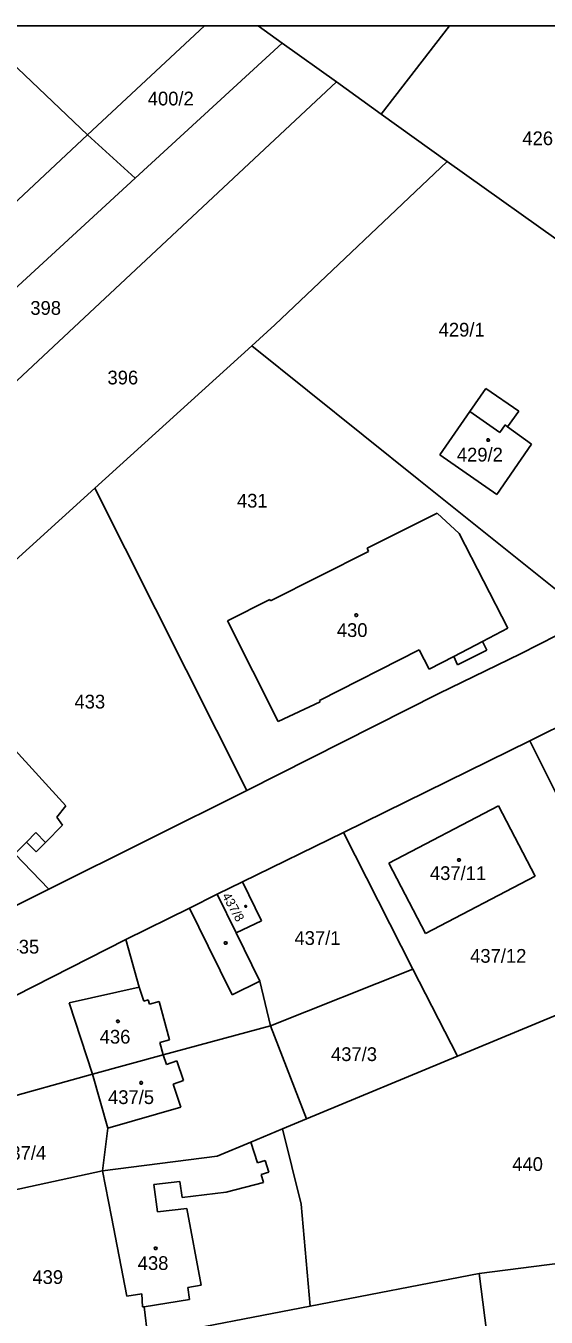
# Model space of a CAD drawing. Extents: x -639621 to -639329, y -1192893 to -1192488.
# Drawn here: x -639495.6 to -639431.2, y -1192647.6 to -1192487.8 of the extents above; entities that cross this region are included whole.
import ezdxf

# ---------------------------------------------------------------- set-up
doc = ezdxf.new("R2010")
doc.units = 0
for name, color, linetype in [('Vrstva 1', 7, 'Continuous'), ('Vrstva 2', 7, 'Continuous'), ('Vrstva 4', 7, 'Continuous'), ('Vrstva 5', 7, 'Continuous'), ('Vrstva 61', 7, 'Continuous')]:
    doc.layers.add(name, color=color, linetype=linetype)

msp = doc.modelspace()

# ---------------------------------------------------------------- linework, layer by layer
at = {"layer": 'Vrstva 1'}
for p, q in [((-639502.15, -1192487.83), (-639487.95, -1192501.33)), ((-639487.95, -1192501.33), (-639473.51, -1192487.83)), ((-639466.87, -1192487.83), (-639463.89, -1192489.96)), ((-639451.66, -1192498.76), (-639443.19, -1192487.83)), ((-639482.08, -1192506.67), (-639463.89, -1192489.96)), ((-639463.89, -1192489.96), (-639457.17, -1192494.75)), ((-639457.17, -1192494.75), (-639502, -1192536.7)), ((-639451.66, -1192498.76), (-639457.17, -1192494.75)), ((-639443.48, -1192504.61), (-639451.66, -1192498.76)), ((-639508.19, -1192520.25), (-639487.95, -1192501.33)), ((-639487.95, -1192501.33), (-639482.08, -1192506.67)), ((-639464.78, -1192524.82), (-639443.48, -1192504.61)), ((-639423.39, -1192518.97), (-639443.48, -1192504.61)), ((-639519.26, -1192540.82), (-639482.08, -1192506.67)), ((-639467.64, -1192527.41), (-639464.78, -1192524.82)), ((-639487.05, -1192545.04), (-639467.64, -1192527.41)), ((-639447, -1192544.01), (-639467.64, -1192527.41)), ((-639440.69, -1192535.56), (-639438.71, -1192532.69)), ((-639438.71, -1192532.69), (-639434.64, -1192535.5)), ((-639444.38, -1192540.91), (-639440.69, -1192535.56)), ((-639434.64, -1192535.5), (-639436.03, -1192537.44)), ((-639436.03, -1192537.44), (-639433.06, -1192539.6)), ((-639433.06, -1192539.6), (-639437.36, -1192545.84)), ((-639437.36, -1192545.84), (-639444.38, -1192540.91)), ((-639425.67, -1192561.08), (-639447, -1192544.01)), ((-639503.65, -1192560.07), (-639487.05, -1192545.04)), ((-639487.05, -1192545.04), (-639468.24, -1192582.43)), ((-639453.4, -1192552.48), (-639444.72, -1192548.13)), ((-639444.72, -1192548.13), (-639442.02, -1192550.64)), ((-639435.99, -1192562.38), (-639442.02, -1192550.64)), ((-639453.2, -1192552.87), (-639453.4, -1192552.48)), ((-639465.33, -1192558.96), (-639453.2, -1192552.87)), ((-639470.65, -1192561.46), (-639465.4, -1192558.83)), ((-639465.4, -1192558.83), (-639465.33, -1192558.96)), ((-639470.65, -1192561.46), (-639464.4, -1192573.92)), ((-639425.67, -1192561.08), (-639434.43, -1192565.52)), ((-639435.99, -1192562.38), (-639439.1, -1192564)), ((-639459.26, -1192571.32), (-639446.93, -1192565.03)), ((-639446.93, -1192565.03), (-639445.72, -1192567.45)), ((-639442.19, -1192566.9), (-639438.6, -1192565.07)), ((-639439.1, -1192564), (-639438.6, -1192565.07)), ((-639442.65, -1192565.85), (-639445.72, -1192567.45)), ((-639434.43, -1192565.52), (-639444.52, -1192570.43)), ((-639442.65, -1192565.85), (-639442.19, -1192566.9)), ((-639433.26, -1192576.32), (-639418.68, -1192568.97)), ((-639444.52, -1192570.43), (-639468.24, -1192582.43)), ((-639464.4, -1192573.92), (-639459.19, -1192571.46)), ((-639459.19, -1192571.46), (-639459.26, -1192571.32)), ((-639456.32, -1192587.64), (-639433.26, -1192576.32)), ((-639433.26, -1192576.32), (-639426.82, -1192589.24)), ((-639497.3, -1192577.02), (-639490.62, -1192584.36)), ((-639468.24, -1192582.43), (-639492.74, -1192594.64)), ((-639490.62, -1192584.36), (-639491.74, -1192585.74)), ((-639437.15, -1192584.36), (-639450.71, -1192591.45)), ((-639432.62, -1192593.04), (-639437.15, -1192584.36)), ((-639491.74, -1192585.74), (-639491.04, -1192586.75)), ((-639491.04, -1192586.75), (-639493.14, -1192588.86)), ((-639468.8, -1192593.76), (-639456.32, -1192587.64)), ((-639456.32, -1192587.64), (-639447.72, -1192604.54)), ((-639496.96, -1192590.28), (-639495.5, -1192588.82)), ((-639495.5, -1192588.82), (-639494.3, -1192590.02)), ((-639493.14, -1192588.86), (-639494.3, -1192590.02)), ((-639492.74, -1192594.64), (-639496.96, -1192590.28)), ((-639450.71, -1192591.45), (-639446.18, -1192600.12)), ((-639471.92, -1192595.29), (-639468.8, -1192593.76)), ((-639466.43, -1192598.56), (-639468.8, -1192593.76)), ((-639446.18, -1192600.12), (-639432.62, -1192593.04)), ((-639492.74, -1192594.64), (-639508.34, -1192602.41)), ((-639475.35, -1192596.99), (-639471.92, -1192595.29)), ((-639471.92, -1192595.29), (-639469.58, -1192600.06)), ((-639483.2, -1192600.88), (-639475.35, -1192596.99)), ((-639469.58, -1192600.06), (-639466.43, -1192598.56)), ((-639469.58, -1192600.06), (-639466.66, -1192606.02)), ((-639506.47, -1192612.71), (-639483.2, -1192600.88)), ((-639483.2, -1192600.88), (-639481.59, -1192606.77)), ((-639465.33, -1192611.56), (-639447.72, -1192604.54)), ((-639447.72, -1192604.54), (-639442.23, -1192615.33)), ((-639442.23, -1192615.33), (-639417.68, -1192605.12)), ((-639490.24, -1192608.71), (-639481.59, -1192606.77)), ((-639466.66, -1192606.02), (-639465.33, -1192611.56)), ((-639487.35, -1192617.54), (-639490.24, -1192608.71)), ((-639478.6, -1192615.16), (-639465.33, -1192611.56)), ((-639465.33, -1192611.56), (-639460.88, -1192623.08)), ((-639487.35, -1192617.54), (-639478.6, -1192615.16)), ((-639460.88, -1192623.08), (-639442.23, -1192615.33)), ((-639504.77, -1192622.38), (-639487.35, -1192617.54)), ((-639487.35, -1192617.54), (-639485.44, -1192624.21)), ((-639485.44, -1192624.21), (-639486.09, -1192629.51)), ((-639467.76, -1192625.94), (-639463.84, -1192624.31)), ((-639463.84, -1192624.31), (-639460.88, -1192623.08)), ((-639463.84, -1192624.31), (-639461.53, -1192633.63)), ((-639467.76, -1192625.94), (-639471.91, -1192627.67)), ((-639486.09, -1192629.51), (-639471.91, -1192627.67)), ((-639502.88, -1192633.13), (-639486.09, -1192629.51)), ((-639486.09, -1192629.51), (-639484.99, -1192635.2)), ((-639460.43, -1192646.25), (-639461.53, -1192633.63)), ((-639484.99, -1192635.2), (-639483.1, -1192645)), ((-639399.34, -1192636.99), (-639439.54, -1192642.21)), ((-639460.43, -1192646.25), (-639439.54, -1192642.21)), ((-639439.54, -1192642.21), (-639433.22, -1192690.86)), ((-639483.1, -1192645), (-639481.24, -1192644.73)), ((-639481.24, -1192644.73), (-639481.16, -1192646.34)), ((-639481.16, -1192646.34), (-639480.96, -1192646.31)), ((-639480.96, -1192646.31), (-639480.51, -1192650.14)), ((-639480.51, -1192650.14), (-639460.43, -1192646.25))]:
    msp.add_line(p, q, dxfattribs=at)
at = {"layer": 'Vrstva 4'}
for p, q in [((-639436.96, -1192538.13), (-639440.69, -1192535.56)), ((-639436.33, -1192537.22), (-639436.96, -1192538.13)), ((-639436.03, -1192537.44), (-639436.33, -1192537.22)), ((-639439.1, -1192564), (-639442.65, -1192565.85)), ((-639495.5, -1192588.82), (-639494.34, -1192587.66)), ((-639494.34, -1192587.66), (-639493.14, -1192588.86)), ((-639475.35, -1192596.99), (-639473.02, -1192601.72)), ((-639473.02, -1192601.72), (-639470.07, -1192607.71)), ((-639481.59, -1192606.77), (-639480.98, -1192608.5)), ((-639466.66, -1192606.02), (-639470.07, -1192607.71)), ((-639480.98, -1192608.5), (-639480.46, -1192608.36)), ((-639480.46, -1192608.36), (-639480.31, -1192608.89)), ((-639479.1, -1192608.56), (-639480.31, -1192608.89)), ((-639477.81, -1192613.29), (-639479.1, -1192608.56)), ((-639479.02, -1192613.62), (-639477.81, -1192613.29)), ((-639479.02, -1192613.62), (-639478.6, -1192615.16)), ((-639478.6, -1192615.16), (-639478.2, -1192616.34)), ((-639476.9, -1192615.9), (-639478.2, -1192616.34)), ((-639476.9, -1192615.9), (-639476.08, -1192618.33)), ((-639476.08, -1192618.33), (-639477.38, -1192618.77)), ((-639477.38, -1192618.77), (-639476.41, -1192621.61)), ((-639485.44, -1192624.21), (-639476.41, -1192621.61)), ((-639467.76, -1192625.94), (-639466.95, -1192628.53)), ((-639465.99, -1192628.23), (-639466.95, -1192628.53)), ((-639465.99, -1192628.23), (-639465.55, -1192629.66)), ((-639479.76, -1192631.18), (-639476.55, -1192630.81)), ((-639476.55, -1192630.81), (-639476.24, -1192632.82)), ((-639465.55, -1192629.66), (-639466.5, -1192629.96)), ((-639466.5, -1192629.96), (-639466.19, -1192630.96)), ((-639479.76, -1192631.18), (-639479.3, -1192634.58)), ((-639476.24, -1192632.82), (-639470.83, -1192632.16)), ((-639470.83, -1192632.16), (-639466.19, -1192630.96)), ((-639479.3, -1192634.58), (-639475.69, -1192634.18)), ((-639473.92, -1192643.67), (-639475.69, -1192634.18)), ((-639473.92, -1192643.67), (-639475.57, -1192643.93)), ((-639475.57, -1192643.93), (-639475.34, -1192645.44)), ((-639480.96, -1192646.31), (-639475.34, -1192645.44))]:
    msp.add_line(p, q, dxfattribs=at)
at = {"layer": 'Vrstva 5'}
for points in [[(-639438.33, -1192538.93), (-639438.24, -1192539.08), (-639438.33, -1192539.23), (-639438.51, -1192539.23), (-639438.6, -1192539.08), (-639438.51, -1192538.93)], [(-639454.64, -1192560.6), (-639454.55, -1192560.75), (-639454.64, -1192560.9), (-639454.82, -1192560.9), (-639454.91, -1192560.75), (-639454.82, -1192560.6)], [(-639441.94, -1192590.89), (-639441.85, -1192591.04), (-639441.94, -1192591.19), (-639442.12, -1192591.19), (-639442.21, -1192591.04), (-639442.12, -1192590.89)], [(-639468.34, -1192596.66), (-639468.28, -1192596.76), (-639468.34, -1192596.86), (-639468.46, -1192596.86), (-639468.52, -1192596.76), (-639468.46, -1192596.66)], [(-639470.79, -1192601.16), (-639470.7, -1192601.31), (-639470.79, -1192601.46), (-639470.97, -1192601.46), (-639471.06, -1192601.31), (-639470.97, -1192601.16)], [(-639484.11, -1192610.85), (-639484.02, -1192611), (-639484.11, -1192611.15), (-639484.29, -1192611.15), (-639484.38, -1192611), (-639484.29, -1192610.85)], [(-639481.23, -1192618.47), (-639481.14, -1192618.62), (-639481.23, -1192618.77), (-639481.41, -1192618.77), (-639481.5, -1192618.62), (-639481.41, -1192618.47)], [(-639479.44, -1192638.94), (-639479.35, -1192639.09), (-639479.44, -1192639.24), (-639479.62, -1192639.24), (-639479.71, -1192639.09), (-639479.62, -1192638.94)]]:
    msp.add_lwpolyline(points, close=True, dxfattribs=at)
at = {"layer": 'Vrstva 61'}
msp.add_lwpolyline([(-639621.26, -1192487.83), (-639329.26, -1192487.83)], dxfattribs=at)

# ---------------------------------------------------------------- texts
at = {"layer": 'Vrstva 2'}
for s, p in [('400/2', (-639480.51, -1192497.68)), ('426', (-639434.19, -1192502.6)), ('398', (-639495.03, -1192523.59)), ('429/1', (-639444.54, -1192526.28)), ('396', (-639485.49, -1192532.2)), ('429/2', (-639442.29, -1192541.74)), ('431', (-639469.48, -1192547.44)), ('430', (-639457.13, -1192563.45)), ('433', (-639489.57, -1192572.3)), ('437/11', (-639445.62, -1192593.52)), ('437/1', (-639462.37, -1192601.55)), ('435', (-639497.72, -1192602.62)), ('437/12', (-639440.65, -1192603.76)), ('436', (-639486.45, -1192613.76)), ('437/3', (-639457.85, -1192615.92)), ('437/5', (-639485.42, -1192621.24)), ('437/4', (-639498.76, -1192628.14)), ('440', (-639435.44, -1192629.52)), ('438', (-639481.75, -1192641.77)), ('439', (-639494.77, -1192643.5))]:
    msp.add_text(s, height=1.7, dxfattribs=at).set_placement(p)
msp.add_text('437/8', height=1.14, rotation=299.3132, dxfattribs=at).set_placement((-639471.37, -1192595.48))

doc.saveas('drawing.dxf')
